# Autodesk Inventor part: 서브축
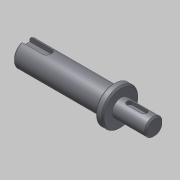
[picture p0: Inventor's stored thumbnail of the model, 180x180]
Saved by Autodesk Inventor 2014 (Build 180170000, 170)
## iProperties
Created: 2018-09
Part Number: 서브축
Document SubType Name: Modeling
Density: 7.86 g/cm^3
Material: 강철, 연강
Appearance: 강철
Mass: 142.801 g
Surface Area: 54.794 cm^2
Volume: 18.1681 cm^3
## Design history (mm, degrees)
sketch "스케치1"
  geometry: L1 (-18.818, -7)-(-18.818, 7) reference; L2 (-41.331, -13.5)-(-41.331, 13.5) reference; L3 (-46.5, 12.249)-(-46.5, -12.249) reference; L4 (-18.331, 0)-(-106.5, 0); L5 (-18.331, 0)-(-18.331, -6); L6 (-18.331, -6)-(-41.331, -6); L7 (-41.331, -12.5)-(-46.5, -12.5); L8 (-46.5, -8.5)-(-106.5, -8.5); L9 (-106.5, -8.5)-(-106.5, 0); L10 (-46.5, -8.5)-(-46.5, -12.5); L11 (-41.331, -6)-(-41.331, -12.5); 2 further points
  constraints: 17 end point, 5 point on line, 3 parallel, 3 perpendicular, 2 collinear, 1 midpoint
  dimensions: "d0" = 23 distance between parallel lines of L2 L5; "d1" = 12 diameter of L6 L4; "d2" = 25 diameter of L7 L4; "d3" = 17 diameter of L8 L4; "d4" = 60 distance of L8.start L8.end
revolve "회전1" sketch "스케치1" stored, may be unused: angle "d5" = 90 deg
chamfer "모따기1" distance "d6" = 1; stored, may be unused: second distance "d7" = 2, angle "d8" = 45 deg
node "작업 평면1"
sketch "스케치2"
  geometry: L1 (11.5, 5)-(11.5, -5) reference; L2 (-5.5, -2)-(4.5, -2); L3 (4.5, 2)-(-5.5, 2); A1 r 2 centre (4.5, 0) between (4.5, -2) and (4.5, 2); A2 r 2 centre (-5.5, 0) between (-5.5, 2) and (-5.5, -2); 2 further points
  constraints: 4 end point, 4 point on circle, 4 tangent, 2 centre point, 1 horizontal alignment, 1 midpoint, 1 parallel, 1 perpendicular
  dimensions: "d9" = 4 distance between parallel lines of L2 L3; "d10" = 14 dimension on A1 A2; "d11" = 5 distance edge to line of A1 L1
extrude "돌출1" cut sketch "스케치2" distance "d12" = 2.5; taper "d13" = 0 deg
node "작업 평면2"
sketch "스케치3"
  geometry: L1 (-30, -7.5)-(-30, 7.5) reference; L2 (-30, 3)-(-15, 3); L3 (-15, -3)-(-30, -3); A1 r 3 centre (-15, 0) between (-15, -3) and (-15, 3); 2 further points
  constraints: 4 end point, 2 perpendicular, 2 point on circle, 2 point on line, 2 tangent, 1 centre point, 1 horizontal alignment, 1 midpoint
  dimensions: "d14" = 6 distance between parallel lines of L3 L2; "d15" = 18 dimension on A1 L1
extrude "돌출2" cut sketch "스케치3" distance "d16" = 3.5; taper "d17" = 0 deg
node "솔리드1"
node "참조1"
node "참조2"
node "참조3"
